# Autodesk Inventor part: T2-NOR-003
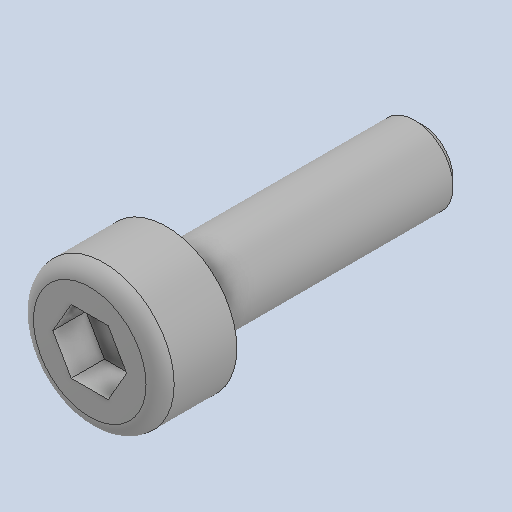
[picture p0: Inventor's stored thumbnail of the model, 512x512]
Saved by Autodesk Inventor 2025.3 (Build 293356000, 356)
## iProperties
Created: 2020-02
Part Number: T2-NOR-003
Material: Genérico
Description: Tornillo de cabeza cilíndrica con hexágono interior M3 × 10 mm
Document SubType Name: Modeling
Designer: Luis MuÃ±oz
Authority: Unknown
Density: 1 g/cm^3
Appearance: Valor por defecto
Project: TESIS 2 - Plataforma mecatrÃ³nica preventiva desacoplada
Sending System: FreeCAD
Preprocessor: Open CASCADE STEP processor 7.3
Title: Tornillo de cabeza cilÃ­ndrica con hexÃ¡gono interior M3 Ã— 10 mm
Author: Author
Revision Number: 00
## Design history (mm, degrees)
feature "Base1"
node "Sólido1"
